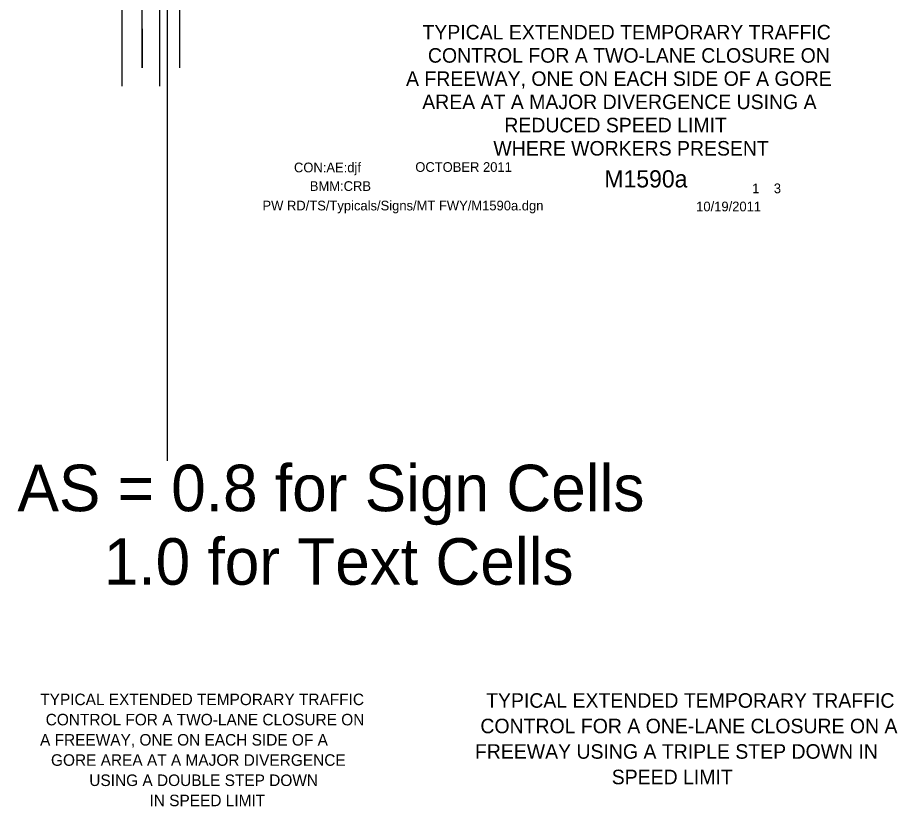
# Model space of a CAD drawing. Extents: x 16728 to 19504, y 5553 to 7079.
# Drawn here: x 16914 to 17477, y 5553 to 6057 of the extents above; entities that cross this region are included whole.
import ezdxf

# ---------------------------------------------------------------- set-up
doc = ezdxf.new("R2010")
doc.units = 0
for name, color, linetype in [('ALI_LEGAL_EX', 7, 'Continuous'), ('BORDER', 7, 'Continuous'), ('BORDER_SIGNAL_WO', 7, 'Continuous')]:
    doc.layers.add(name, color=color, linetype=linetype)

msp = doc.modelspace()

# ---------------------------------------------------------------- linework, layer by layer
at = {"layer": 'ALI_LEGAL_EX'}
for p, q in [((16980.68, 6877.04), (16980.68, 6013.12)), ((17004.68, 6877.04), (17004.68, 6013.12)), ((16993.65, 6024.8), (16993.65, 6525.15)), ((17017.65, 6024.8), (17017.65, 6525.15)), ((17009.75, 5773.57), (17009.75, 6383.76))]:
    msp.add_line(p, q, dxfattribs=at)
msp.add_lwpolyline([(16993.65, 6049.8), (16993.65, 6024.8)], dxfattribs=at)

# ---------------------------------------------------------------- texts
at = {"layer": 'BORDER'}
for s, height, p in [('TYPICAL EXTENDED TEMPORARY TRAFFIC', 9.3, (17172.85, 6043.01)), ('CONTROL FOR A TWO-LANE CLOSURE ON', 9.3, (17176.35, 6028.16)), ('A FREEWAY, ONE ON EACH SIDE OF A GORE', 9.3, (17162.37, 6013.31)), ('AREA AT A MAJOR DIVERGENCE USING A', 9.3, (17172.72, 5998.46)), ('REDUCED SPEED LIMIT', 9.3, (17225.22, 5983.61)), ('WHERE WORKERS PRESENT', 9.3, (17218.22, 5968.76)), ('TYPICAL EXTENDED TEMPORARY TRAFFIC', 7.3743, (16928.4, 5617.4)), ('TYPICAL EXTENDED TEMPORARY TRAFFIC', 9.3, (17213.56, 5615.73)), ('CONTROL FOR A TWO-LANE CLOSURE ON', 7.3743, (16931.9, 5604.47)), ('CONTROL FOR A ONE-LANE CLOSURE ON A', 9.3, (17209.93, 5599.43)), ('A FREEWAY, ONE ON EACH SIDE OF A  ', 7.3743, (16928.28, 5591.55)), ('FREEWAY USING A TRIPLE STEP DOWN IN ', 9.3, (17206.43, 5583.13)), ('GORE AREA AT A MAJOR DIVERGENCE ', 7.3743, (16935.28, 5578.62)), ('USING A DOUBLE STEP DOWN ', 7.3743, (16959.78, 5565.7)), ('SPEED LIMIT', 9.3, (17293.93, 5566.83)), ('IN SPEED LIMIT', 7.3743, (16998.28, 5552.78))]:
    msp.add_text(s, height=height, dxfattribs=at).set_placement(p)
at = {"layer": 'BORDER_SIGNAL_WO'}
for s, height, p in [('CON:AE:djf  ', 6.2, (17090.69, 5958.06)), ('    OCTOBER 2011    ', 6.2, (17159.08, 5958.34)), ('    M1590a   ', 11, (17272.86, 5948.38)), ('BMM:CRB   ', 6.2, (17100.81, 5946.17)), (' 1    3 ', 6.2, (17381.45, 5944.7)), ('PW RD/TS/Typicals/Signs/MT FWY/M1590a.dgn      ', 6.2, (17070.55, 5933.71)), ('10/19/2011    ', 6.2, (17347.93, 5933.13)), ('AS = 0.8 for Sign Cells', 29.7271, (16913.84, 5741.4)), ('     1.0 for Text Cells', 29.7271, (16913.84, 5694.4))]:
    msp.add_text(s, height=height, dxfattribs=at).set_placement(p)

doc.saveas('drawing.dxf')
